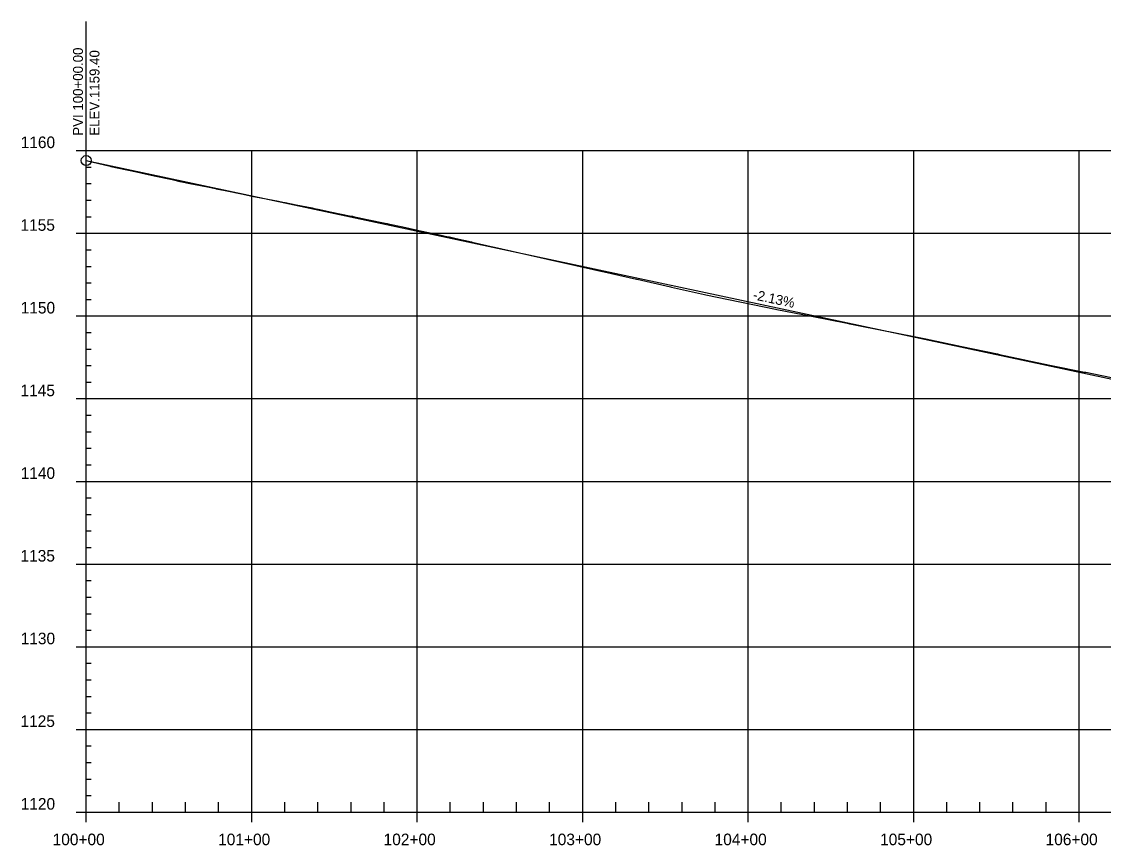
# Model space of a CAD drawing. Extents: x 688474 to 694748, y 765018 to 767373.
# Drawn here: x 690916 to 691570, y 766506 to 767004 of the extents above; entities that cross this region are included whole.
import ezdxf

# ---------------------------------------------------------------- set-up
doc = ezdxf.new("R2010")
doc.units = 0
for name, color, linetype in [('30', 7, 'Continuous'), ('37', 7, 'Continuous'), ('R_Exist Surface', 7, 'Continuous'), ('R_Vert Alg', 7, 'Continuous'), ('R_Vert Alg Annot', 7, 'Continuous')]:
    doc.layers.add(name, color=color, linetype=linetype)

msp = doc.modelspace()

# ---------------------------------------------------------------- linework, layer by layer
at = {"layer": '37'}
for p, q in [((690949.19, 766926.49), (690955.19, 766926.49)), ((690949.19, 766926.49), (690955.19, 766926.49)), ((690955.19, 766526.49), (690955.19, 766926.49)), ((690955.19, 766926.49), (693355.19, 766926.49)), ((690955.19, 766926.49), (693355.19, 766926.49)), ((691055.19, 766526.49), (691055.19, 766926.49)), ((691155.19, 766526.49), (691155.19, 766926.49)), ((691255.19, 766526.49), (691255.19, 766926.49)), ((691355.19, 766526.49), (691355.19, 766926.49)), ((691455.19, 766526.49), (691455.19, 766926.49)), ((691555.19, 766526.49), (691555.19, 766926.49)), ((690955.19, 766916.49), (690958.19, 766916.49)), ((690955.19, 766906.49), (690958.19, 766906.49)), ((690955.19, 766896.49), (690958.19, 766896.49)), ((690955.19, 766886.49), (690958.19, 766886.49)), ((690949.19, 766876.49), (690955.19, 766876.49)), ((690955.19, 766876.49), (693355.19, 766876.49)), ((690955.19, 766866.49), (690958.19, 766866.49)), ((690955.19, 766856.49), (690958.19, 766856.49)), ((690955.19, 766846.49), (690958.19, 766846.49)), ((690955.19, 766836.49), (690958.19, 766836.49)), ((690949.19, 766826.49), (690955.19, 766826.49)), ((690955.19, 766826.49), (693355.19, 766826.49)), ((690955.19, 766816.49), (690958.19, 766816.49)), ((690955.19, 766806.49), (690958.19, 766806.49)), ((690955.19, 766796.49), (690958.19, 766796.49)), ((690955.19, 766786.49), (690958.19, 766786.49)), ((690949.19, 766776.49), (690955.19, 766776.49)), ((690955.19, 766776.49), (693355.19, 766776.49)), ((690955.19, 766766.49), (690958.19, 766766.49)), ((690955.19, 766756.49), (690958.19, 766756.49)), ((690955.19, 766746.49), (690958.19, 766746.49)), ((690955.19, 766736.49), (690958.19, 766736.49)), ((690949.19, 766726.49), (690955.19, 766726.49)), ((690955.19, 766726.49), (693355.19, 766726.49)), ((690955.19, 766716.49), (690958.19, 766716.49)), ((690955.19, 766706.49), (690958.19, 766706.49)), ((690955.19, 766696.49), (690958.19, 766696.49)), ((690955.19, 766686.49), (690958.19, 766686.49)), ((690949.19, 766676.49), (690955.19, 766676.49)), ((690955.19, 766676.49), (693355.19, 766676.49)), ((690955.19, 766666.49), (690958.19, 766666.49)), ((690955.19, 766656.49), (690958.19, 766656.49)), ((690955.19, 766646.49), (690958.19, 766646.49)), ((690955.19, 766636.49), (690958.19, 766636.49)), ((690949.19, 766626.49), (690955.19, 766626.49)), ((690955.19, 766626.49), (693355.19, 766626.49)), ((690955.19, 766616.49), (690958.19, 766616.49)), ((690955.19, 766606.49), (690958.19, 766606.49)), ((690955.19, 766596.49), (690958.19, 766596.49)), ((690955.19, 766586.49), (690958.19, 766586.49)), ((690949.19, 766576.49), (690955.19, 766576.49)), ((690955.19, 766576.49), (693355.19, 766576.49)), ((690955.19, 766566.49), (690958.19, 766566.49)), ((690955.19, 766556.49), (690958.19, 766556.49)), ((690955.19, 766546.49), (690958.19, 766546.49)), ((690955.19, 766536.49), (690958.19, 766536.49)), ((690975.19, 766526.49), (690975.19, 766532.49)), ((690995.19, 766526.49), (690995.19, 766532.49)), ((691015.19, 766526.49), (691015.19, 766532.49)), ((691035.19, 766526.49), (691035.19, 766532.49)), ((691075.19, 766526.49), (691075.19, 766532.49)), ((691095.19, 766526.49), (691095.19, 766532.49)), ((691115.19, 766526.49), (691115.19, 766532.49)), ((691135.19, 766526.49), (691135.19, 766532.49)), ((691175.19, 766526.49), (691175.19, 766532.49)), ((691195.19, 766526.49), (691195.19, 766532.49)), ((691215.19, 766526.49), (691215.19, 766532.49)), ((691235.19, 766526.49), (691235.19, 766532.49)), ((691275.19, 766526.49), (691275.19, 766532.49)), ((691295.19, 766526.49), (691295.19, 766532.49)), ((691315.19, 766526.49), (691315.19, 766532.49)), ((691335.19, 766526.49), (691335.19, 766532.49)), ((691375.19, 766526.49), (691375.19, 766532.49)), ((691395.19, 766526.49), (691395.19, 766532.49)), ((691415.19, 766526.49), (691415.19, 766532.49)), ((691435.19, 766526.49), (691435.19, 766532.49)), ((691475.19, 766526.49), (691475.19, 766532.49)), ((691495.19, 766526.49), (691495.19, 766532.49)), ((691515.19, 766526.49), (691515.19, 766532.49)), ((691535.19, 766526.49), (691535.19, 766532.49)), ((690949.19, 766526.49), (690955.19, 766526.49)), ((690955.19, 766526.49), (693355.19, 766526.49)), ((690955.19, 766520.49), (690955.19, 766526.49)), ((691055.19, 766520.49), (691055.19, 766526.49)), ((691155.19, 766520.49), (691155.19, 766526.49)), ((691255.19, 766520.49), (691255.19, 766526.49)), ((691355.19, 766520.49), (691355.19, 766526.49)), ((691455.19, 766520.49), (691455.19, 766526.49)), ((691555.19, 766520.49), (691555.19, 766526.49))]:
    msp.add_line(p, q, dxfattribs=at)
at = {"layer": 'R_Exist Surface'}
msp.add_lwpolyline([(690955.19, 766920.47), (690969.7, 766917.03), (690970.07, 766916.96), (690974.87, 766915.93), (690985.59, 766913.62), (690990.87, 766912.47), (690996.32, 766911.28), (691007.04, 766908.91), (691011.84, 766907.84), (691012.03, 766907.8), (691017.77, 766906.66), (691028.5, 766904.49), (691033.26, 766903.52), (691033.61, 766903.46), (691039.22, 766902.31), (691049.95, 766900.1), (691054.4, 766899.18), (691055.19, 766899.02), (691060.68, 766897.96), (691071.4, 766895.84), (691075.06, 766895.12), (691075.31, 766895.07), (691082.13, 766893.71), (691091.73, 766891.78), (691092.86, 766891.55), (691095.39, 766891.03), (691095.42, 766891.02), (691103.58, 766889.34), (691114.31, 766887.12), (691116.03, 766886.77), (691116.5, 766886.65), (691125.04, 766884.88), (691135.76, 766882.65), (691136.96, 766882.4), (691137.58, 766882.24), (691146.49, 766880.33), (691155.41, 766878.42), (691156.12, 766878.24), (691157.22, 766878.01), (691167.94, 766875.71), (691173.97, 766874.42), (691174.64, 766874.25), (691178.67, 766873.33), (691187.95, 766871.22), (691188.3, 766871.12), (691201.74, 766868.06), (691201.97, 766868), (691223.18, 766863.27), (691223.34, 766863.23), (691240.2, 766859.48), (691244.71, 766858.46), (691266.17, 766853.62), (691266.35, 766853.58), (691287.67, 766848.77), (691288, 766848.7), (691308.21, 766844.09), (691308.79, 766843.96), (691328.73, 766839.41), (691329.57, 766839.23), (691350.21, 766835.01), (691351.08, 766834.83), (691371.73, 766830.62), (691372.59, 766830.43), (691393.41, 766826.32), (691394.47, 766826.11), (691415.04, 766822.04), (691416.33, 766821.78), (691417.7, 766821.51), (691438.93, 766817.32), (691440.09, 766817.09), (691461.53, 766812.85), (691462.52, 766812.64), (691484.25, 766808.07), (691505.93, 766803.51), (691506.97, 766803.28), (691521.38, 766800.24), (691522.26, 766800.05), (691523.14, 766799.86), (691537.53, 766796.82), (691538.47, 766796.63), (691558.46, 766792.61), (691559.29, 766792.44), (691579.55, 766788.37)], dxfattribs=at)
at = {"layer": 'R_Vert Alg'}
msp.add_line((690955.19, 766920.47), (691792.26, 766741.85), dxfattribs=at)
msp.add_circle((690955.19, 766920.47), 3, dxfattribs=at)
at = {"layer": 'R_Vert Alg Annot'}
msp.add_line((690955.19, 766920.47), (690955.19, 767004.47), dxfattribs=at)

# ---------------------------------------------------------------- texts
at = {"layer": '30'}
for s, p in [('1160', (690915.57, 766927.99)), ('1160', (690915.57, 766927.99)), ('1155', (690915.45, 766877.99)), ('1150', (690915.57, 766827.99)), ('1145', (690915.45, 766777.99)), ('1140', (690915.57, 766727.99)), ('1135', (690915.45, 766677.99)), ('1130', (690915.57, 766627.99)), ('1125', (690915.45, 766577.99)), ('1120', (690915.57, 766527.99)), ('100+00', (690934.88, 766506.49)), ('101+00', (691034.88, 766506.49)), ('102+00', (691134.88, 766506.49)), ('103+00', (691234.88, 766506.49)), ('104+00', (691334.88, 766506.49)), ('105+00', (691434.88, 766506.49)), ('106+00', (691534.88, 766506.49))]:
    msp.add_text(s, height=7, dxfattribs=at).set_placement(p)
at = {"layer": 'R_Vert Alg Annot'}
for s, rotation, p in [('PVI 100+00.00', 90, (690953.19, 766935.47)), ('ELEV.1159.40', 90, (690963.19, 766935.47)), ('-2.13%', 347.95443, (691357.71, 766836.62))]:
    msp.add_text(s, height=6, rotation=rotation, dxfattribs=at).set_placement(p)

doc.saveas('drawing.dxf')
